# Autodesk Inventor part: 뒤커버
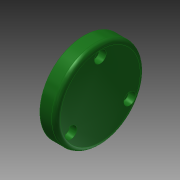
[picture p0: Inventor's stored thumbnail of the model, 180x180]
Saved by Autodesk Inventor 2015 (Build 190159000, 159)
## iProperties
Created: 2015-11
Part Number: 뒤커버
Material: 알루미늄 6061
Document SubType Name: Modeling
Designer: mduedu
Density: 1 g/cm^3
Appearance: 매끄러움 - 짙은 산림 녹색
Author: mduedu
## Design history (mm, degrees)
sketch "스케치5"
  geometry: C1 r 30 at (0, 0); 2 further points
  constraints: 2 coincident, 1 centre point
  dimensions: "d66" = 60 diameter of C1
extrude "돌출2" new body sketch "스케치5" distance "d67" = 11; taper "d68" = 0 deg
sketch "스케치6"
  geometry: C1 r 16 at (0, 0); 1 further point
  constraints: 1 centre point, 1 coincident
  dimensions: "d69" = 32 diameter of C1
extrude "돌출3" join sketch "스케치6" distance "d70" = 3; taper "d71" = 0 deg
hole "구멍5" diameter "d74" = 27; stored, may be unused: countersink angle "d78" = 90 deg, drill point angle "d80" = 0 deg; dims "d75" = 6, "d76" = 4, "d77" = 2, "d79" = 10, "d100" = 10, "d101" = 10
fillet "모깎기8" dims "d82" = 3
fillet "모깎기9" dims "d83" = 3
fillet "모깎기10" dims "d84" = 0.3
sketch "스케치7" dims "d85" = 46
  geometry: 3 further points
  constraints: 2 vertical alignment, 1 coincident, 2 other
hole "구멍6" sketch "스케치7" at (0, 23) diameter "d86" = 4.5; stored, may be unused: countersink angle "d90" = 90 deg, drill point angle "d92" = 0 deg; dims "d87" = 6, "d88" = 8, "d89" = 4.6, "d91" = 10
node "솔리드2"
pattern_circular "원형 패턴3" dims angle "d94" = 360 deg
